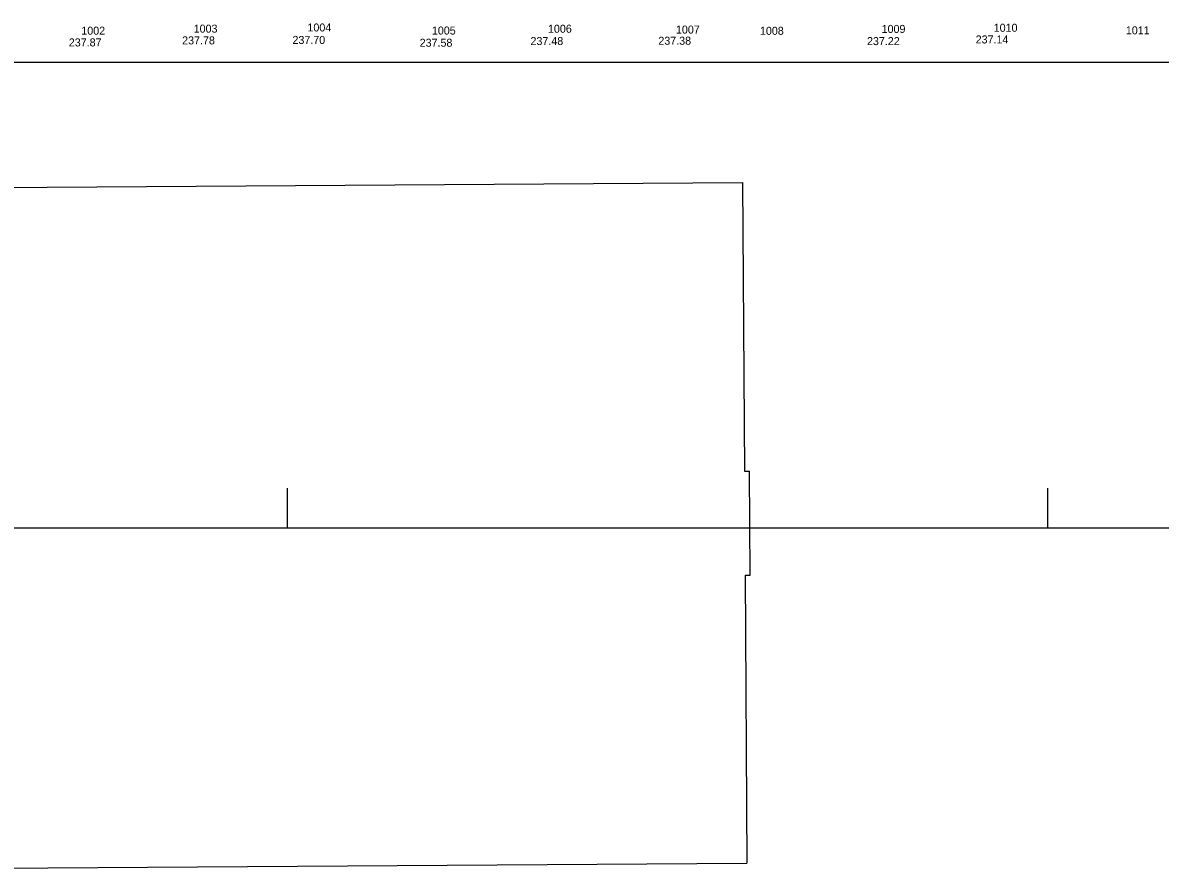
# Model space of a CAD drawing. Extents: x -264205 to -263615, y -1242401 to -1242031.
# Drawn here: x -263925.3 to -263854.3, y -1242365.3 to -1242312.5 of the extents above; entities that cross this region are included whole.
import ezdxf

# ---------------------------------------------------------------- set-up
doc = ezdxf.new("R2010")
doc.units = 0
for name, color, linetype in [('BODY_SYMBOL A CISLO_2-1', 7, 'Continuous'), ('BODY_VYSKA_2-1', 7, 'Continuous'), ('KOORDINACNA_SITUACIA_DSP', 7, 'Continuous'), ('RAM_NA_TLAC_1-250_SITUACIA_2-1', 7, 'Continuous')]:
    doc.layers.add(name, color=color, linetype=linetype)

msp = doc.modelspace()

# ---------------------------------------------------------------- linework, layer by layer
at = {"layer": 'KOORDINACNA_SITUACIA_DSP'}
for p, q in [((-264038.443, -1242314.982), (-263836.403, -1242314.982)), ((-263976.89, -1242323.14), (-263880.39, -1242322.51)), ((-263880.39, -1242322.51), (-263880.27, -1242340.53)), ((-263880.27, -1242340.53), (-263879.95, -1242340.53)), ((-263879.9, -1242347.02), (-263879.95, -1242340.53)), ((-263880.23, -1242347.02), (-263879.9, -1242347.02)), ((-263880.23, -1242347.02), (-263880.12, -1242365.01)), ((-263928.07, -1242365.32), (-263880.12, -1242365.01))]:
    msp.add_line(p, q, dxfattribs=at)
at = {"layer": 'RAM_NA_TLAC_1-250_SITUACIA_2-1'}
for p, q in [((-263908.833, -1242341.585), (-263908.833, -1242344.085)), ((-263861.333, -1242341.585), (-263861.333, -1242344.085))]:
    msp.add_line(p, q, dxfattribs=at)
msp.add_lwpolyline([(-264151.333, -1242269.835), (-263718.833, -1242269.835), (-263718.833, -1242344.085), (-264151.333, -1242344.085)], close=True, dxfattribs=at)

# ---------------------------------------------------------------- texts
at = {"layer": 'BODY_SYMBOL A CISLO_2-1'}
for s, p in [('1002', (-263921.69, -1242313.271)), ('1003', (-263914.671, -1242313.143)), ('1004', (-263907.565, -1242313.07)), ('1005', (-263899.791, -1242313.261)), ('1006', (-263892.539, -1242313.149)), ('1007', (-263884.544, -1242313.201)), ('1008', (-263879.296, -1242313.278)), ('1009', (-263871.695, -1242313.161)), ('1010', (-263864.694, -1242313.087)), ('1011', (-263856.44, -1242313.25))]:
    msp.add_text(s, height=0.5, dxfattribs=at).set_placement(p)
at = {"layer": 'BODY_VYSKA_2-1'}
for s, p in [('237.87', (-263922.473, -1242314.003)), ('237.78', (-263915.392, -1242313.877)), ('237.70', (-263908.5, -1242313.849)), ('237.58', (-263900.555, -1242314.023)), ('237.48', (-263893.631, -1242313.917)), ('237.38', (-263885.644, -1242313.898)), ('237.22', (-263872.61, -1242313.921)), ('237.14', (-263865.821, -1242313.818))]:
    msp.add_text(s, height=0.5, dxfattribs=at).set_placement(p)

doc.saveas('drawing.dxf')
